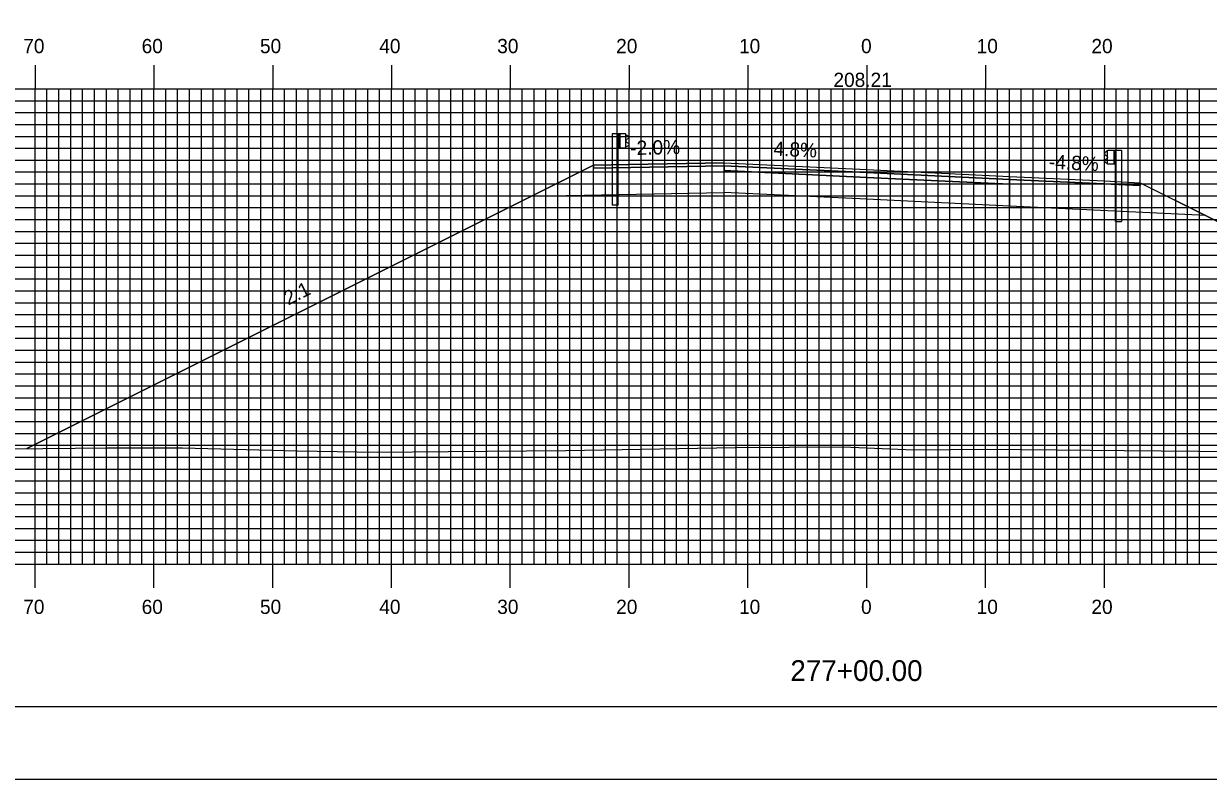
# Model space of a CAD drawing. Extents: x 1810193 to 1810536, y 442591 to 442811.
# Drawn here: x 1810287.9 to 1810387.6, y 442590.5 to 442654.1 of the extents above; entities that cross this region are included whole.
import ezdxf

# ---------------------------------------------------------------- set-up
doc = ezdxf.new("R2010")
doc.units = 0
for name, color, linetype in [('ANNOTATION', 7, 'Continuous'), ('BORDER', 7, 'Continuous'), ('D_Guardrail_Beam_Lt', 7, 'Continuous'), ('D_Guardrail_Beam_Rt', 7, 'Continuous'), ('D_Roadway_Centerline', 7, 'Continuous'), ('D_Roadway_Centerline_Text', 7, 'Continuous'), ('D_Roadway_Edge_Shoulder', 7, 'Continuous'), ('D_Roadway_Edge_TW', 7, 'Continuous'), ('D_Roadway_Pavement', 7, 'Continuous'), ('D_Roadway_SlopeLines', 7, 'Continuous'), ('D_Roadway_SubGrade', 7, 'Continuous'), ('H_V ANNOTATION', 7, 'Continuous'), ('MAJOR', 7, 'Continuous'), ('MINOR', 7, 'Continuous'), ('PLOT BOUNDARY', 7, 'Continuous'), ('S_Roadway_Centerline', 7, 'Continuous')]:
    doc.layers.add(name, color=color, linetype=linetype)

msp = doc.modelspace()

# ---------------------------------------------------------------- linework, layer by layer
at = {"layer": 'BORDER'}
msp.add_lwpolyline([(1810209.263, 442596.665), (1810529.263, 442596.665), (1810529.263, 442806.665), (1810209.263, 442806.665)], close=True, dxfattribs=at)
at = {"layer": 'D_Guardrail_Beam_Lt'}
for p, q in [((1810337.434, 442644.87), (1810337.434, 442638.87)), ((1810337.905, 442644.87), (1810337.434, 442644.87)), ((1810338.593, 442644.87), (1810337.905, 442644.87)), ((1810337.905, 442644.87), (1810337.905, 442643.703)), ((1810337.968, 442644.87), (1810337.968, 442643.703)), ((1810338.072, 442644.87), (1810338.072, 442643.703)), ((1810338.593, 442643.703), (1810338.593, 442644.87)), ((1810338.593, 442644.786), (1810338.667, 442644.772)), ((1810338.597, 442644.321), (1810338.597, 442644.251)), ((1810338.826, 442644.522), (1810338.631, 442644.386)), ((1810338.631, 442644.187), (1810338.826, 442644.051)), ((1810338.683, 442644.765), (1810338.826, 442644.665)), ((1810338.826, 442643.907), (1810338.683, 442643.807)), ((1810337.905, 442643.703), (1810338.593, 442643.703)), ((1810337.926, 442638.87), (1810337.926, 442643.703)), ((1810338.667, 442643.801), (1810338.593, 442643.786)), ((1810337.926, 442638.87), (1810337.434, 442638.87))]:
    msp.add_line(p, q, dxfattribs=at)
for centre, major_axis, start_param, end_param in [((1810338.676, 442644.321), (-0.0789, 0), 5.323254, 6.283185), ((1810338.676, 442644.251), (-0.0789, 0), 6.283185, 7.243116), ((1810338.659, 442644.731), (0.0417, 0), 0.959931, 1.376053), ((1810338.776, 442644.593), (0.0877, 0), 5.323254, 7.243116), ((1810338.776, 442643.979), (0.0877, 0), 5.323254, 7.243116), ((1810338.659, 442643.841), (0.0417, 0), 4.907132, 5.323254)]:
    msp.add_ellipse(centre, major_axis=major_axis, ratio=0.995501, start_param=start_param, end_param=end_param, dxfattribs=at)
at = {"layer": 'D_Guardrail_Beam_Rt'}
for p, q in [((1810379.044, 442643.389), (1810378.901, 442643.289)), ((1810378.901, 442643.146), (1810379.096, 442643.01)), ((1810379.134, 442643.41), (1810379.06, 442643.396)), ((1810379.13, 442642.945), (1810379.13, 442642.875)), ((1810379.134, 442643.494), (1810379.822, 442643.494)), ((1810379.134, 442642.327), (1810379.134, 442643.494)), ((1810379.655, 442643.494), (1810379.655, 442642.327)), ((1810379.759, 442643.494), (1810379.759, 442642.327)), ((1810379.822, 442643.494), (1810380.293, 442643.494)), ((1810379.822, 442643.494), (1810379.822, 442642.327)), ((1810380.293, 442643.494), (1810380.293, 442637.494)), ((1810379.096, 442642.811), (1810378.901, 442642.675)), ((1810378.901, 442642.531), (1810379.044, 442642.431)), ((1810379.06, 442642.425), (1810379.134, 442642.41)), ((1810379.822, 442642.327), (1810379.134, 442642.327)), ((1810379.801, 442637.494), (1810379.801, 442642.327)), ((1810379.801, 442637.494), (1810380.293, 442637.494))]:
    msp.add_line(p, q, dxfattribs=at)
for centre, major_axis, start_param, end_param in [((1810378.951, 442643.217), (-0.0877, 0), 5.323254, 7.243116), ((1810379.068, 442643.355), (-0.0417, 0), 4.907132, 5.323254), ((1810379.051, 442642.945), (0.0789, 0), 0, 0.959931), ((1810378.951, 442642.603), (-0.0877, 0), 5.323254, 7.243116), ((1810379.068, 442642.465), (-0.0417, 0), 0.959931, 1.376053), ((1810379.051, 442642.875), (0.0789, 0), 5.323254, 6.283185)]:
    msp.add_ellipse(centre, major_axis=major_axis, ratio=0.995501, start_param=start_param, end_param=end_param, dxfattribs=at)
at = {"layer": 'D_Roadway_Centerline'}
msp.add_lwpolyline([(1810288.183, 442618.386), (1810330.655, 442639.622), (1810335.863, 442642.226), (1810338.863, 442642.286), (1810346.863, 442642.446), (1810358.863, 442641.87), (1810370.863, 442641.294), (1810378.863, 442640.91), (1810381.863, 442640.766), (1810387.395, 442638.001), (1810427.801, 442617.797)], dxfattribs=at)
at = {"layer": 'D_Roadway_Edge_Shoulder'}
for points in [[(1810346.863, 442642.446), (1810338.863, 442642.286), (1810338.863, 442642.286), (1810335.863, 442642.226), (1810335.863, 442641.976), (1810346.863, 442642.196)], [(1810370.863, 442641.294), (1810378.863, 442640.91), (1810378.863, 442640.91), (1810381.863, 442640.766), (1810381.863, 442640.516), (1810370.863, 442641.044)]]:
    msp.add_lwpolyline(points, close=True, dxfattribs=at)
at = {"layer": 'D_Roadway_Edge_TW'}
msp.add_lwpolyline([(1810346.863, 442642.196), (1810346.863, 442642.446), (1810358.863, 442641.87), (1810370.863, 442641.294), (1810370.863, 442641.044), (1810358.863, 442641.62)], close=True, dxfattribs=at)
at = {"layer": 'D_Roadway_Pavement'}
msp.add_lwpolyline([(1810346.863, 442641.78), (1810346.863, 442642.196), (1810358.863, 442641.62), (1810370.863, 442641.044), (1810370.863, 442640.628), (1810358.863, 442641.204)], close=True, dxfattribs=at)
for points in [[(1810346.863, 442642.196), (1810346.863, 442641.78)], [(1810370.863, 442641.044), (1810370.863, 442640.628)]]:
    msp.add_lwpolyline(points, dxfattribs=at)
at = {"layer": 'D_Roadway_SlopeLines'}
for points in [[(1810335.863, 442642.226), (1810288.183, 442618.386)], [(1810381.863, 442640.766), (1810427.801, 442617.797)]]:
    msp.add_lwpolyline(points, dxfattribs=at)
at = {"layer": 'D_Roadway_SubGrade'}
for points in [[(1810346.863, 442641.78), (1810346.863, 442642.196), (1810335.863, 442641.976), (1810335.863, 442642.226), (1810330.655, 442639.622), (1810346.863, 442639.946)], [(1810346.863, 442639.946), (1810346.863, 442642.196), (1810346.863, 442641.78), (1810358.863, 442641.204), (1810370.863, 442640.628), (1810370.863, 442641.044), (1810370.863, 442638.794), (1810358.863, 442639.37)], [(1810370.863, 442640.628), (1810370.863, 442641.044), (1810381.863, 442640.516), (1810381.863, 442640.766), (1810387.395, 442638.001), (1810370.863, 442638.794)]]:
    msp.add_lwpolyline(points, close=True, dxfattribs=at)
at = {"layer": 'MAJOR'}
for p, q in [((1810288.863, 442650.669), (1810288.863, 442648.665)), ((1810298.863, 442650.669), (1810298.863, 442648.665)), ((1810308.863, 442650.669), (1810308.863, 442648.665)), ((1810318.863, 442650.669), (1810318.863, 442648.665)), ((1810328.863, 442650.669), (1810328.863, 442648.665)), ((1810338.863, 442650.669), (1810338.863, 442648.665)), ((1810348.863, 442650.669), (1810348.863, 442648.665)), ((1810358.863, 442650.669), (1810358.863, 442648.665)), ((1810368.863, 442650.669), (1810368.863, 442648.665)), ((1810378.863, 442650.669), (1810378.863, 442648.665)), ((1810218.863, 442648.665), (1810498.863, 442648.665)), ((1810218.863, 442648.665), (1810498.863, 442648.665)), ((1810288.863, 442608.665), (1810288.863, 442648.665)), ((1810298.863, 442608.665), (1810298.863, 442648.665)), ((1810308.863, 442608.665), (1810308.863, 442648.665)), ((1810318.863, 442608.665), (1810318.863, 442648.665)), ((1810328.863, 442608.665), (1810328.863, 442648.665)), ((1810338.863, 442608.665), (1810338.863, 442648.665)), ((1810348.863, 442608.665), (1810348.863, 442648.665)), ((1810358.863, 442608.665), (1810358.863, 442648.665)), ((1810368.863, 442608.665), (1810368.863, 442648.665)), ((1810378.863, 442608.665), (1810378.863, 442648.665)), ((1810218.863, 442643.665), (1810498.863, 442643.665)), ((1810218.863, 442638.665), (1810498.863, 442638.665)), ((1810218.863, 442633.665), (1810498.863, 442633.665)), ((1810218.863, 442628.665), (1810498.863, 442628.665)), ((1810218.863, 442623.665), (1810498.863, 442623.665)), ((1810218.863, 442618.665), (1810498.863, 442618.665)), ((1810218.863, 442613.665), (1810498.863, 442613.665)), ((1810218.863, 442608.665), (1810498.863, 442608.665)), ((1810218.863, 442608.665), (1810498.863, 442608.665)), ((1810288.863, 442606.661), (1810288.863, 442608.665)), ((1810298.863, 442606.661), (1810298.863, 442608.665)), ((1810308.863, 442606.661), (1810308.863, 442608.665)), ((1810318.863, 442606.661), (1810318.863, 442608.665)), ((1810328.863, 442606.661), (1810328.863, 442608.665)), ((1810338.863, 442606.661), (1810338.863, 442608.665)), ((1810348.863, 442606.661), (1810348.863, 442608.665)), ((1810358.863, 442606.661), (1810358.863, 442608.665)), ((1810368.863, 442606.661), (1810368.863, 442608.665)), ((1810378.863, 442606.661), (1810378.863, 442608.665))]:
    msp.add_line(p, q, dxfattribs=at)
at = {"layer": 'MINOR'}
for p, q in [((1810289.863, 442608.665), (1810289.863, 442648.665)), ((1810290.863, 442608.665), (1810290.863, 442648.665)), ((1810291.863, 442608.665), (1810291.863, 442648.665)), ((1810292.863, 442608.665), (1810292.863, 442648.665)), ((1810293.863, 442608.665), (1810293.863, 442648.665)), ((1810294.863, 442608.665), (1810294.863, 442648.665)), ((1810295.863, 442608.665), (1810295.863, 442648.665)), ((1810296.863, 442608.665), (1810296.863, 442648.665)), ((1810297.863, 442608.665), (1810297.863, 442648.665)), ((1810299.863, 442608.665), (1810299.863, 442648.665)), ((1810300.863, 442608.665), (1810300.863, 442648.665)), ((1810301.863, 442608.665), (1810301.863, 442648.665)), ((1810302.863, 442608.665), (1810302.863, 442648.665)), ((1810303.863, 442608.665), (1810303.863, 442648.665)), ((1810304.863, 442608.665), (1810304.863, 442648.665)), ((1810305.863, 442608.665), (1810305.863, 442648.665)), ((1810306.863, 442608.665), (1810306.863, 442648.665)), ((1810307.863, 442608.665), (1810307.863, 442648.665)), ((1810309.863, 442608.665), (1810309.863, 442648.665)), ((1810310.863, 442608.665), (1810310.863, 442648.665)), ((1810311.863, 442608.665), (1810311.863, 442648.665)), ((1810312.863, 442608.665), (1810312.863, 442648.665)), ((1810313.863, 442608.665), (1810313.863, 442648.665)), ((1810314.863, 442608.665), (1810314.863, 442648.665)), ((1810315.863, 442608.665), (1810315.863, 442648.665)), ((1810316.863, 442608.665), (1810316.863, 442648.665)), ((1810317.863, 442608.665), (1810317.863, 442648.665)), ((1810319.863, 442608.665), (1810319.863, 442648.665)), ((1810320.863, 442608.665), (1810320.863, 442648.665)), ((1810321.863, 442608.665), (1810321.863, 442648.665)), ((1810322.863, 442608.665), (1810322.863, 442648.665)), ((1810323.863, 442608.665), (1810323.863, 442648.665)), ((1810324.863, 442608.665), (1810324.863, 442648.665)), ((1810325.863, 442608.665), (1810325.863, 442648.665)), ((1810326.863, 442608.665), (1810326.863, 442648.665)), ((1810327.863, 442608.665), (1810327.863, 442648.665)), ((1810329.863, 442608.665), (1810329.863, 442648.665)), ((1810330.863, 442608.665), (1810330.863, 442648.665)), ((1810331.863, 442608.665), (1810331.863, 442648.665)), ((1810332.863, 442608.665), (1810332.863, 442648.665)), ((1810333.863, 442608.665), (1810333.863, 442648.665)), ((1810334.863, 442608.665), (1810334.863, 442648.665)), ((1810335.863, 442608.665), (1810335.863, 442648.665)), ((1810336.863, 442608.665), (1810336.863, 442648.665)), ((1810337.863, 442608.665), (1810337.863, 442648.665)), ((1810339.863, 442608.665), (1810339.863, 442648.665)), ((1810340.863, 442608.665), (1810340.863, 442648.665)), ((1810341.863, 442608.665), (1810341.863, 442648.665)), ((1810342.863, 442608.665), (1810342.863, 442648.665)), ((1810343.863, 442608.665), (1810343.863, 442648.665)), ((1810344.863, 442608.665), (1810344.863, 442648.665)), ((1810345.863, 442608.665), (1810345.863, 442648.665)), ((1810346.863, 442608.665), (1810346.863, 442648.665)), ((1810347.863, 442608.665), (1810347.863, 442648.665)), ((1810349.863, 442608.665), (1810349.863, 442648.665)), ((1810350.863, 442608.665), (1810350.863, 442648.665)), ((1810351.863, 442608.665), (1810351.863, 442648.665)), ((1810352.863, 442608.665), (1810352.863, 442648.665)), ((1810353.863, 442608.665), (1810353.863, 442648.665)), ((1810354.863, 442608.665), (1810354.863, 442648.665)), ((1810355.863, 442608.665), (1810355.863, 442648.665)), ((1810356.863, 442608.665), (1810356.863, 442648.665)), ((1810357.863, 442608.665), (1810357.863, 442648.665)), ((1810359.863, 442608.665), (1810359.863, 442648.665)), ((1810360.863, 442608.665), (1810360.863, 442648.665)), ((1810361.863, 442608.665), (1810361.863, 442648.665)), ((1810362.863, 442608.665), (1810362.863, 442648.665)), ((1810363.863, 442608.665), (1810363.863, 442648.665)), ((1810364.863, 442608.665), (1810364.863, 442648.665)), ((1810365.863, 442608.665), (1810365.863, 442648.665)), ((1810366.863, 442608.665), (1810366.863, 442648.665)), ((1810367.863, 442608.665), (1810367.863, 442648.665)), ((1810369.863, 442608.665), (1810369.863, 442648.665)), ((1810370.863, 442608.665), (1810370.863, 442648.665)), ((1810371.863, 442608.665), (1810371.863, 442648.665)), ((1810372.863, 442608.665), (1810372.863, 442648.665)), ((1810373.863, 442608.665), (1810373.863, 442648.665)), ((1810374.863, 442608.665), (1810374.863, 442648.665)), ((1810375.863, 442608.665), (1810375.863, 442648.665)), ((1810376.863, 442608.665), (1810376.863, 442648.665)), ((1810377.863, 442608.665), (1810377.863, 442648.665)), ((1810379.863, 442608.665), (1810379.863, 442648.665)), ((1810380.863, 442608.665), (1810380.863, 442648.665)), ((1810381.863, 442608.665), (1810381.863, 442648.665)), ((1810382.863, 442608.665), (1810382.863, 442648.665)), ((1810383.863, 442608.665), (1810383.863, 442648.665)), ((1810384.863, 442608.665), (1810384.863, 442648.665)), ((1810385.863, 442608.665), (1810385.863, 442648.665)), ((1810386.863, 442608.665), (1810386.863, 442648.665)), ((1810218.863, 442647.665), (1810498.863, 442647.665)), ((1810218.863, 442646.665), (1810498.863, 442646.665)), ((1810218.863, 442645.665), (1810498.863, 442645.665)), ((1810218.863, 442644.665), (1810498.863, 442644.665)), ((1810218.863, 442642.665), (1810498.863, 442642.665)), ((1810218.863, 442641.665), (1810498.863, 442641.665)), ((1810218.863, 442640.665), (1810498.863, 442640.665)), ((1810218.863, 442639.665), (1810498.863, 442639.665)), ((1810218.863, 442637.665), (1810498.863, 442637.665)), ((1810218.863, 442636.665), (1810498.863, 442636.665)), ((1810218.863, 442635.665), (1810498.863, 442635.665)), ((1810218.863, 442634.665), (1810498.863, 442634.665)), ((1810218.863, 442632.665), (1810498.863, 442632.665)), ((1810218.863, 442631.665), (1810498.863, 442631.665)), ((1810218.863, 442630.665), (1810498.863, 442630.665)), ((1810218.863, 442629.665), (1810498.863, 442629.665)), ((1810218.863, 442627.665), (1810498.863, 442627.665)), ((1810218.863, 442626.665), (1810498.863, 442626.665)), ((1810218.863, 442625.665), (1810498.863, 442625.665)), ((1810218.863, 442624.665), (1810498.863, 442624.665)), ((1810218.863, 442622.665), (1810498.863, 442622.665)), ((1810218.863, 442621.665), (1810498.863, 442621.665)), ((1810218.863, 442620.665), (1810498.863, 442620.665)), ((1810218.863, 442619.665), (1810498.863, 442619.665)), ((1810218.863, 442617.665), (1810498.863, 442617.665)), ((1810218.863, 442616.665), (1810498.863, 442616.665)), ((1810218.863, 442615.665), (1810498.863, 442615.665)), ((1810218.863, 442614.665), (1810498.863, 442614.665)), ((1810218.863, 442612.665), (1810498.863, 442612.665)), ((1810218.863, 442611.665), (1810498.863, 442611.665)), ((1810218.863, 442610.665), (1810498.863, 442610.665)), ((1810218.863, 442609.665), (1810498.863, 442609.665))]:
    msp.add_line(p, q, dxfattribs=at)
at = {"layer": 'PLOT BOUNDARY'}
msp.add_lwpolyline([(1810193.077, 442590.547), (1810533.077, 442590.547), (1810533.077, 442810.547), (1810193.077, 442810.547)], close=True, dxfattribs=at)
at = {"layer": 'S_Roadway_Centerline'}
msp.add_lwpolyline([(1810218.863, 442618.088), (1810224.287, 442618.039), (1810231.814, 442617.976), (1810235.981, 442618.017), (1810239.793, 442618.017), (1810248.187, 442618.173), (1810255.371, 442618.067), (1810259.191, 442618.042), (1810277.828, 442618.24), (1810282.029, 442618.248), (1810286.786, 442618.374), (1810294.965, 442618.444), (1810301.272, 442618.444), (1810310.911, 442618.196), (1810317.65, 442618.08), (1810323.636, 442618.14), (1810333.526, 442618.22), (1810347.794, 442618.473), (1810356.877, 442618.527), (1810362.801, 442618.283), (1810369.049, 442618.334), (1810380.513, 442618.211), (1810392.975, 442618.124)], dxfattribs=at)

# ---------------------------------------------------------------- texts
at = {"layer": 'ANNOTATION'}
for s, rotation, p in [('-2.0%', 1.14576, (1810338.97, 442643.089)), ('4.8%', 357.25191, (1810350.993, 442643.05)), ('-4.8%', 357.25191, (1810374.172, 442641.938)), ('2:1', 26.56505, (1810310.169, 442630.415))]:
    msp.add_text(s, height=1.2, rotation=rotation, dxfattribs=at).set_placement(p)
at = {"layer": 'D_Roadway_Centerline'}
for s, p in [('C', (1810358.858, 442641.87)), ('L', (1810358.863, 442641.863))]:
    msp.add_text(s, height=0.0146, dxfattribs=at).set_placement(p)
at = {"layer": 'D_Roadway_Centerline_Text'}
msp.add_text('208.21', height=1.2, dxfattribs=at).set_placement((1810356.059, 442648.822))
at = {"layer": 'H_V ANNOTATION'}
for s, height, p in [('70', 1.2, (1810287.868, 442651.665)), ('60', 1.2, (1810297.836, 442651.665)), ('50', 1.2, (1810307.793, 442651.665)), ('40', 1.2, (1810317.836, 442651.665)), ('30', 1.2, (1810327.761, 442651.665)), ('20', 1.2, (1810337.771, 442651.665)), ('10', 1.2, (1810348.114, 442651.665)), ('0', 1.2, (1810358.382, 442651.665)), ('10', 1.2, (1810368.114, 442651.665)), ('20', 1.2, (1810377.771, 442651.665)), ('70', 1.2, (1810287.868, 442604.465)), ('60', 1.2, (1810297.836, 442604.465)), ('50', 1.2, (1810307.793, 442604.465)), ('40', 1.2, (1810317.836, 442604.465)), ('30', 1.2, (1810327.761, 442604.465)), ('20', 1.2, (1810337.771, 442604.465)), ('10', 1.2, (1810348.114, 442604.465)), ('0', 1.2, (1810358.382, 442604.465)), ('10', 1.2, (1810368.114, 442604.465)), ('20', 1.2, (1810377.771, 442604.465)), ('277+00.00', 1.75, (1810352.433, 442598.821))]:
    msp.add_text(s, height=height, dxfattribs=at).set_placement(p)

doc.saveas('drawing.dxf')
